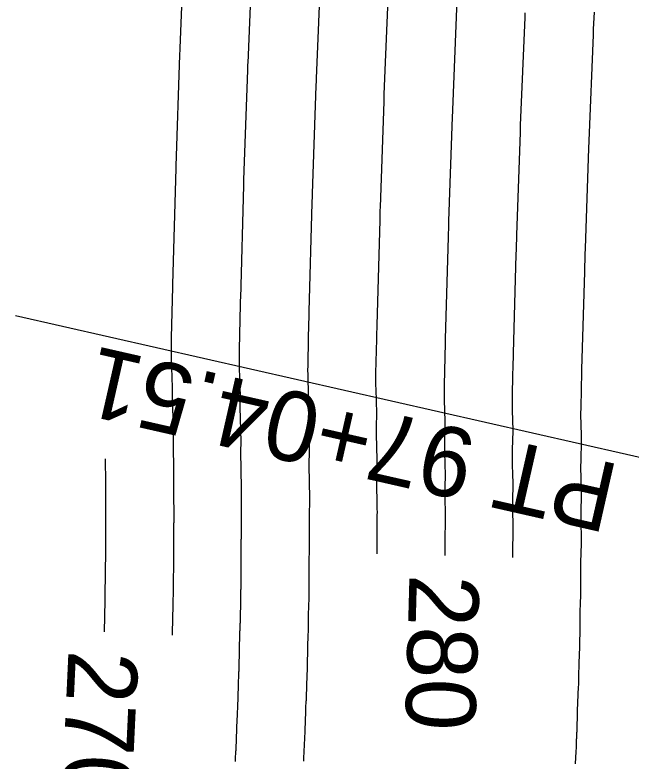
# Model space of a CAD drawing. Extents: x 1710723 to 1713003, y 548603 to 551142.
# Drawn here: x 1712129.7 to 1712182.6, y 549615.6 to 549679.7 of the extents above; entities that cross this region are included whole.
import ezdxf

# ---------------------------------------------------------------- set-up
doc = ezdxf.new("R2010")
doc.units = 0
for name, color, linetype in [('R_Contour Annot', 7, 'Continuous'), ('R_Contours', 7, 'Continuous'), ('R_Horz Alg', 7, 'Continuous'), ('R_Horz Alg Annot', 7, 'Continuous')]:
    doc.layers.add(name, color=color, linetype=linetype)

msp = doc.modelspace()

# ---------------------------------------------------------------- linework, layer by layer
at = {"layer": 'R_Contours'}
for points in [[(1712144.267, 549686.914), (1712143.856, 549676.857), (1712143.854, 549676.791), (1712143.851, 549676.725), (1712143.835, 549676.293), (1712143.835, 549676.289), (1712143.508, 549666.704), (1712143.506, 549666.66), (1712143.505, 549666.616), (1712143.503, 549666.571), (1712143.502, 549666.527), (1712143.225, 549656.545), (1712143.224, 549656.485), (1712143.222, 549656.425), (1712143.221, 549656.365), (1712143.219, 549656.305), (1712143.121, 549651.99), (1712143.114, 549651.558), (1712143.113, 549651.125), (1712143.117, 549650.693), (1712143.126, 549650.261), (1712143.199, 549647.69), (1712143.2, 549647.646), (1712143.201, 549647.603), (1712143.202, 549647.592), (1712143.202, 549647.581), (1712143.202, 549647.571), (1712143.201, 549647.56), (1712143.196, 549647.343), (1712143.196, 549647.303), (1712143.195, 549647.263), (1712143.196, 549647.224), (1712143.196, 549647.184), (1712143.272, 549643.792), (1712143.273, 549643.758), (1712143.273, 549643.724), (1712143.273, 549643.69), (1712143.273, 549643.656), (1712143.27, 549643.52), (1712143.27, 549643.486), (1712143.27, 549643.452), (1712143.27, 549643.418), (1712143.27, 549643.384), (1712143.318, 549639.926), (1712143.318, 549639.915), (1712143.322, 549639.508), (1712143.322, 549639.47), (1712143.322, 549639.433), (1712143.322, 549639.395), (1712143.321, 549639.357), (1712143.317, 549639.207), (1712143.317, 549639.169), (1712143.316, 549639.132), (1712143.316, 549639.094), (1712143.316, 549639.057), (1712143.328, 549636.181), (1712143.328, 549636.141), (1712143.328, 549636.101), (1712143.327, 549636.061), (1712143.326, 549636.021), (1712143.321, 549635.862), (1712143.32, 549635.822), (1712143.319, 549635.782), (1712143.319, 549635.742), (1712143.318, 549635.702), (1712143.304, 549632.289), (1712143.304, 549632.272), (1712143.303, 549632.237), (1712143.302, 549632.22), (1712143.293, 549631.259), (1712143.292, 549631.222), (1712143.291, 549631.185), (1712143.29, 549631.148), (1712143.289, 549631.111), (1712143.283, 549630.963), (1712143.282, 549630.926), (1712143.281, 549630.889), (1712143.28, 549630.851), (1712143.279, 549630.814), (1712143.246, 549628.537), (1712143.245, 549628.492), (1712143.244, 549628.447), (1712143.242, 549628.402), (1712143.24, 549628.357), (1712143.232, 549628.178), (1712143.23, 549628.133), (1712143.228, 549628.088), (1712143.226, 549628.043), (1712143.225, 549627.998), (1712143.19, 549626.418)], [(1712148.624, 549615.564), (1712148.628, 549615.652), (1712148.633, 549615.741), (1712148.638, 549615.829), (1712148.644, 549615.918), (1712148.667, 549616.272), (1712148.673, 549616.36), (1712148.678, 549616.449), (1712148.682, 549616.537), (1712148.686, 549616.626), (1712148.791, 549619.218), (1712148.799, 549619.434), (1712148.807, 549619.649), (1712148.815, 549619.864), (1712148.823, 549620.079), (1712148.862, 549621.25), (1712148.864, 549621.311), (1712148.866, 549621.371), (1712148.869, 549621.431), (1712148.873, 549621.491), (1712148.887, 549621.733), (1712148.89, 549621.793), (1712148.893, 549621.853), (1712148.895, 549621.913), (1712148.897, 549621.974), (1712148.935, 549623.285), (1712148.936, 549623.31), (1712148.937, 549623.336), (1712148.938, 549623.361), (1712148.939, 549623.387), (1712148.945, 549623.488), (1712148.946, 549623.514), (1712148.947, 549623.539), (1712148.948, 549623.565), (1712148.949, 549623.59), (1712149.015, 549626.598), (1712149.018, 549626.68), (1712149.02, 549626.763), (1712149.023, 549626.845), (1712149.027, 549626.928), (1712149.043, 549627.258), (1712149.047, 549627.341), (1712149.05, 549627.423), (1712149.052, 549627.506), (1712149.053, 549627.588), (1712149.082, 549629.55), (1712149.083, 549629.619), (1712149.085, 549629.688), (1712149.087, 549629.757), (1712149.09, 549629.826), (1712149.101, 549630.103), (1712149.103, 549630.172), (1712149.105, 549630.241), (1712149.107, 549630.31), (1712149.108, 549630.38), (1712149.116, 549631.191), (1712149.116, 549631.213), (1712149.117, 549631.235), (1712149.118, 549631.278), (1712149.119, 549631.3), (1712149.119, 549631.322), (1712149.132, 549634.4), (1712149.133, 549634.477), (1712149.134, 549634.554), (1712149.135, 549634.631), (1712149.137, 549634.708), (1712149.147, 549635.016), (1712149.149, 549635.093), (1712149.15, 549635.17), (1712149.151, 549635.247), (1712149.151, 549635.324), (1712149.14, 549637.838), (1712149.14, 549637.912), (1712149.141, 549637.986), (1712149.142, 549638.061), (1712149.143, 549638.135), (1712149.151, 549638.469), (1712149.152, 549638.526), (1712149.152, 549638.582), (1712149.152, 549638.638), (1712149.152, 549638.694), (1712149.149, 549639.028), (1712149.149, 549639.05), (1712149.106, 549642.189), (1712149.105, 549642.258), (1712149.105, 549642.328), (1712149.105, 549642.398), (1712149.106, 549642.468), (1712149.111, 549642.747), (1712149.112, 549642.816), (1712149.112, 549642.886), (1712149.111, 549642.956), (1712149.11, 549643.025), (1712149.043, 549646.012), (1712149.042, 549646.096), (1712149.041, 549646.181), (1712149.042, 549646.265), (1712149.043, 549646.35), (1712149.054, 549646.836), (1712149.055, 549646.846), (1712149.055, 549646.856), (1712149.055, 549646.866), (1712149.054, 549646.876), (1712149.053, 549646.947), (1712149.052, 549646.957), (1712148.984, 549649.353), (1712148.976, 549649.756), (1712148.972, 549650.158), (1712148.973, 549650.561), (1712148.98, 549650.964), (1712149.067, 549654.814), (1712149.071, 549654.955), (1712149.074, 549655.096), (1712149.078, 549655.237), (1712149.081, 549655.378), (1712149.35, 549665.046), (1712149.353, 549665.166), (1712149.357, 549665.287), (1712149.36, 549665.407), (1712149.365, 549665.528), (1712149.686, 549674.953), (1712149.689, 549675.02), (1712149.701, 549675.349), (1712149.703, 549675.406), (1712149.705, 549675.462), (1712149.708, 549675.519), (1712149.71, 549675.575), (1712150.112, 549685.428)], [(1712155.958, 549683.942), (1712155.561, 549674.239), (1712155.559, 549674.186), (1712155.557, 549674.133), (1712155.555, 549674.081), (1712155.553, 549674.028), (1712155.539, 549673.654), (1712155.538, 549673.616), (1712155.221, 549664.351), (1712155.215, 549664.155), (1712155.209, 549663.958), (1712155.203, 549663.761), (1712155.197, 549663.565), (1712154.938, 549654.212), (1712154.932, 549653.99), (1712154.926, 549653.768), (1712154.92, 549653.546), (1712154.915, 549653.324), (1712154.838, 549649.938), (1712154.832, 549649.564), (1712154.831, 549649.191), (1712154.834, 549648.818), (1712154.843, 549648.445), (1712154.905, 549646.224), (1712154.906, 549646.187), (1712154.907, 549646.15), (1712154.908, 549646.14), (1712154.908, 549646.131), (1712154.908, 549646.121), (1712154.907, 549646.112), (1712154.89, 549645.356), (1712154.888, 549645.227), (1712154.887, 549645.098), (1712154.888, 549644.969), (1712154.89, 549644.84), (1712154.948, 549642.259), (1712154.95, 549642.154), (1712154.95, 549642.048), (1712154.95, 549641.943), (1712154.949, 549641.837), (1712154.942, 549641.415), (1712154.941, 549641.31), (1712154.94, 549641.204), (1712154.94, 549641.099), (1712154.941, 549640.993), (1712154.98, 549638.174), (1712154.98, 549638.164), (1712154.98, 549638.145), (1712154.98, 549638.142), (1712154.983, 549637.835), (1712154.983, 549637.783), (1712154.983, 549637.731), (1712154.982, 549637.679), (1712154.981, 549637.627), (1712154.969, 549637.064), (1712154.967, 549636.952), (1712154.965, 549636.841), (1712154.964, 549636.73), (1712154.965, 549636.619), (1712154.974, 549634.467), (1712154.974, 549634.353), (1712154.973, 549634.239), (1712154.971, 549634.125), (1712154.968, 549634.01), (1712154.954, 549633.554), (1712154.95, 549633.44), (1712154.948, 549633.326), (1712154.946, 549633.212), (1712154.946, 549633.097), (1712154.934, 549630.354), (1712154.934, 549630.338), (1712154.934, 549630.322), (1712154.933, 549630.306), (1712154.933, 549630.29), (1712154.931, 549630.227), (1712154.93, 549630.211), (1712154.93, 549630.195), (1712154.929, 549630.179), (1712154.929, 549630.163), (1712154.922, 549629.501), (1712154.921, 549629.399), (1712154.919, 549629.298), (1712154.916, 549629.197), (1712154.912, 549629.095), (1712154.896, 549628.69), (1712154.892, 549628.589), (1712154.889, 549628.487), (1712154.887, 549628.386), (1712154.885, 549628.285), (1712154.861, 549626.64), (1712154.859, 549626.519), (1712154.855, 549626.399), (1712154.851, 549626.279), (1712154.846, 549626.159), (1712154.823, 549625.678), (1712154.817, 549625.558), (1712154.813, 549625.438), (1712154.809, 549625.318), (1712154.806, 549625.198), (1712154.747, 549622.543), (1712154.746, 549622.506), (1712154.744, 549622.469), (1712154.743, 549622.432), (1712154.741, 549622.396), (1712154.733, 549622.249), (1712154.731, 549622.212), (1712154.73, 549622.176), (1712154.728, 549622.139), (1712154.727, 549622.102), (1712154.695, 549620.984), (1712154.692, 549620.897), (1712154.689, 549620.81), (1712154.685, 549620.724), (1712154.68, 549620.637), (1712154.66, 549620.29), (1712154.655, 549620.204), (1712154.651, 549620.117), (1712154.647, 549620.03), (1712154.644, 549619.943), (1712154.61, 549618.929), (1712154.603, 549618.731), (1712154.596, 549618.533), (1712154.588, 549618.335), (1712154.581, 549618.137), (1712154.488, 549615.841), (1712154.482, 549615.715), (1712154.476, 549615.589)], [(1712160.796, 549633.406), (1712160.796, 549633.459), (1712160.796, 549633.61), (1712160.789, 549635.4), (1712160.789, 549635.548), (1712160.79, 549635.696), (1712160.791, 549635.844), (1712160.794, 549635.992), (1712160.812, 549636.785), (1712160.813, 549636.833), (1712160.814, 549636.881), (1712160.814, 549636.928), (1712160.814, 549636.976), (1712160.811, 549637.256), (1712160.811, 549637.27), (1712160.812, 549637.292), (1712160.812, 549637.299), (1712160.777, 549639.798), (1712160.775, 549639.939), (1712160.775, 549640.08), (1712160.776, 549640.222), (1712160.778, 549640.363), (1712160.787, 549640.928), (1712160.789, 549641.069), (1712160.789, 549641.21), (1712160.788, 549641.351), (1712160.785, 549641.493), (1712160.737, 549643.668), (1712160.734, 549643.842), (1712160.733, 549644.016), (1712160.734, 549644.189), (1712160.737, 549644.363), (1712160.761, 549645.388), (1712160.761, 549645.406), (1712160.76, 549645.423), (1712160.759, 549645.492), (1712160.701, 549647.537), (1712160.693, 549647.88), (1712160.69, 549648.224), (1712160.691, 549648.568), (1712160.697, 549648.912), (1712160.763, 549651.833), (1712160.77, 549652.136), (1712160.778, 549652.439), (1712160.786, 549652.742), (1712160.794, 549653.045), (1712161.044, 549662.083), (1712161.052, 549662.356), (1712161.06, 549662.629), (1712161.069, 549662.902), (1712161.078, 549663.175), (1712161.389, 549672.279), (1712161.391, 549672.334), (1712161.405, 549672.707), (1712161.407, 549672.756), (1712161.409, 549672.805), (1712161.41, 549672.853), (1712161.412, 549672.902), (1712161.803, 549682.456)], [(1712167.648, 549680.971), (1712167.264, 549671.565), (1712167.262, 549671.521), (1712167.26, 549671.476), (1712167.258, 549671.431), (1712167.257, 549671.386), (1712167.243, 549671.013), (1712167.241, 549670.96), (1712167.24, 549670.943), (1712166.935, 549661.999), (1712166.923, 549661.65), (1712166.912, 549661.301), (1712166.902, 549660.951), (1712166.892, 549660.602), (1712166.65, 549651.878), (1712166.639, 549651.494), (1712166.63, 549651.11), (1712166.62, 549650.726), (1712166.611, 549650.342), (1712166.555, 549647.885), (1712166.55, 549647.571), (1712166.549, 549647.257), (1712166.552, 549646.943), (1712166.559, 549646.629), (1712166.612, 549644.759), (1712166.613, 549644.728), (1712166.614, 549644.696), (1712166.614, 549644.68), (1712166.614, 549644.665), (1712166.584, 549643.37), (1712166.58, 549643.152), (1712166.579, 549642.933), (1712166.58, 549642.715), (1712166.583, 549642.496), (1712166.623, 549640.726), (1712166.626, 549640.549), (1712166.628, 549640.372), (1712166.627, 549640.195), (1712166.625, 549640.018), (1712166.613, 549639.311), (1712166.611, 549639.134), (1712166.61, 549638.957), (1712166.611, 549638.78), (1712166.612, 549638.603), (1712166.643, 549636.423), (1712166.643, 549636.41), (1712166.642, 549636.383), (1712166.642, 549636.369), (1712166.644, 549636.117), (1712166.645, 549636.073), (1712166.644, 549636.03), (1712166.644, 549635.986), (1712166.643, 549635.943), (1712166.62, 549634.92), (1712166.616, 549634.735), (1712166.614, 549634.55), (1712166.613, 549634.366), (1712166.613, 549634.181), (1712166.617, 549633.249)], [(1712172.437, 549633.091), (1712172.437, 549633.183), (1712172.438, 549633.405), (1712172.441, 549633.627), (1712172.446, 549633.849), (1712172.474, 549635.1), (1712172.475, 549635.14), (1712172.475, 549635.179), (1712172.475, 549635.219), (1712172.475, 549635.258), (1712172.473, 549635.483), (1712172.473, 549635.499), (1712172.474, 549635.532), (1712172.474, 549635.548), (1712172.448, 549637.407), (1712172.446, 549637.62), (1712172.445, 549637.833), (1712172.446, 549638.045), (1712172.449, 549638.258), (1712172.463, 549639.109), (1712172.466, 549639.322), (1712172.466, 549639.534), (1712172.464, 549639.747), (1712172.461, 549639.96), (1712172.43, 549641.324), (1712172.426, 549641.588), (1712172.424, 549641.851), (1712172.426, 549642.114), (1712172.43, 549642.377), (1712172.467, 549643.941), (1712172.467, 549643.955), (1712172.467, 549643.969), (1712172.465, 549644.027), (1712172.417, 549645.721), (1712172.411, 549646.005), (1712172.408, 549646.29), (1712172.409, 549646.575), (1712172.414, 549646.859), (1712172.46, 549648.909), (1712172.471, 549649.345), (1712172.481, 549649.781), (1712172.493, 549650.218), (1712172.504, 549650.654), (1712172.739, 549659.121), (1712172.751, 549659.546), (1712172.764, 549659.972), (1712172.778, 549660.397), (1712172.792, 549660.822), (1712173.092, 549669.606), (1712173.093, 549669.649), (1712173.095, 549669.692), (1712173.109, 549670.066), (1712173.11, 549670.106), (1712173.112, 549670.147), (1712173.113, 549670.188), (1712173.115, 549670.229), (1712173.493, 549679.485), (1712173.51, 549679.896)], [(1712179.425, 549679.959), (1712179.402, 549679.469), (1712179.38, 549678.979), (1712179.359, 549678.489), (1712179.338, 549677.999), (1712178.966, 549668.892), (1712178.965, 549668.855), (1712178.963, 549668.818), (1712178.962, 549668.782), (1712178.961, 549668.745), (1712178.947, 549668.371), (1712178.945, 549668.32), (1712178.943, 549668.269), (1712178.649, 549659.646), (1712178.632, 549659.145), (1712178.616, 549658.643), (1712178.601, 549658.141), (1712178.587, 549657.64), (1712178.354, 549649.235), (1712178.343, 549648.844), (1712178.333, 549648.453), (1712178.323, 549648.061), (1712178.314, 549647.67), (1712178.272, 549645.833), (1712178.268, 549645.578), (1712178.267, 549645.323), (1712178.27, 549645.068), (1712178.275, 549644.812), (1712178.318, 549643.294), (1712178.32, 549643.243), (1712178.32, 549643.23), (1712178.32, 549643.217), (1712178.275, 549641.286), (1712178.271, 549641.027), (1712178.269, 549640.768), (1712178.27, 549640.509), (1712178.275, 549640.25), (1712178.298, 549639.193), (1712178.303, 549638.945), (1712178.305, 549638.696), (1712178.304, 549638.448), (1712178.301, 549638.2), (1712178.285, 549637.206), (1712178.281, 549636.957), (1712178.28, 549636.709), (1712178.281, 549636.46), (1712178.283, 549636.212), (1712178.305, 549634.672), (1712178.305, 549634.653), (1712178.304, 549634.616), (1712178.304, 549634.597), (1712178.306, 549634.399), (1712178.306, 549634.364), (1712178.306, 549634.328), (1712178.305, 549634.293), (1712178.305, 549634.258), (1712178.269, 549632.696), (1712178.265, 549632.478), (1712178.262, 549632.26), (1712178.261, 549632.042), (1712178.261, 549631.823), (1712178.265, 549630.951), (1712178.265, 549630.733), (1712178.263, 549630.514), (1712178.259, 549630.296), (1712178.253, 549630.078), (1712178.217, 549628.913), (1712178.211, 549628.663), (1712178.205, 549628.413), (1712178.202, 549628.163), (1712178.2, 549627.913), (1712178.194, 549626.485), (1712178.194, 549626.449), (1712178.193, 549626.412), (1712178.192, 549626.376), (1712178.191, 549626.339), (1712178.186, 549626.194), (1712178.185, 549626.157), (1712178.184, 549626.121), (1712178.183, 549626.085), (1712178.182, 549626.048), (1712178.179, 549625.673), (1712178.178, 549625.599), (1712178.176, 549625.524), (1712178.174, 549625.45), (1712178.171, 549625.375), (1712178.117, 549624.031), (1712178.111, 549623.858), (1712178.106, 549623.685), (1712178.101, 549623.513), (1712178.098, 549623.34), (1712178.088, 549622.649), (1712178.085, 549622.476), (1712178.08, 549622.304), (1712178.074, 549622.131), (1712178.067, 549621.958), (1712178.002, 549620.627), (1712177.991, 549620.383), (1712177.982, 549620.139), (1712177.974, 549619.896), (1712177.968, 549619.652), (1712177.939, 549618.352), (1712177.937, 549618.271), (1712177.934, 549618.189), (1712177.931, 549618.107), (1712177.927, 549618.025), (1712177.909, 549617.698), (1712177.905, 549617.616), (1712177.901, 549617.534), (1712177.898, 549617.453), (1712177.895, 549617.371), (1712177.881, 549616.863), (1712177.877, 549616.751), (1712177.873, 549616.64), (1712177.867, 549616.528), (1712177.861, 549616.416), (1712177.8, 549615.359)], [(1712137.375, 549626.688), (1712137.435, 549629.398), (1712137.435, 549629.412), (1712137.436, 549629.427), (1712137.438, 549629.464), (1712137.438, 549629.478), (1712137.438, 549629.485), (1712137.476, 549632.079), (1712137.477, 549632.099), (1712137.478, 549632.123), (1712137.478, 549632.138), (1712137.489, 549633.248), (1712137.489, 549633.256), (1712137.505, 549637.005), (1712137.505, 549637.016), (1712137.505, 549637.035), (1712137.505, 549637.037), (1712137.492, 549640.276), (1712137.492, 549640.285), (1712137.487, 549640.801), (1712137.477, 549641.567)]]:
    msp.add_lwpolyline(points, dxfattribs=at)
at = {"layer": 'R_Horz Alg'}
msp.add_arc((1711727.021, 549745.305), 532.984, 270.64281, 347.20664, dxfattribs=at)
at = {"layer": 'R_Horz Alg Annot'}
msp.add_lwpolyline([(1712246.774, 549627.283), (1712129.753, 549653.855)], dxfattribs=at)

# ---------------------------------------------------------------- texts
at = {"layer": 'R_Contour Annot'}
for s, rotation, p in [('280', 268.45309, (1712163.574, 549631.677)), ('270', 267.34159, (1712134.301, 549625.175))]:
    msp.add_text(s, height=6, rotation=rotation, dxfattribs=at).set_placement(p)
at = {"layer": 'R_Horz Alg Annot'}
msp.add_text('PT 97+04.51', height=6, rotation=167.20664, dxfattribs=at).set_placement((1712181.776, 549641.017))

doc.saveas('drawing.dxf')
